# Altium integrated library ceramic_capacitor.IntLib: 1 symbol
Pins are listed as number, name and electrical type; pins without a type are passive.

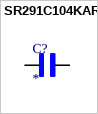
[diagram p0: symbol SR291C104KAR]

## SR291C104KAR
designator C?
SR Series 5.08 x 5.08 mm 100 nF 100 V Â±10 % Tol. X7R Radial Lead/SkyCapÂ®; MF: AVX; MP: SR291C104KAR
footprint CAPRR254W50L508T317H508
pins: 1, 2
